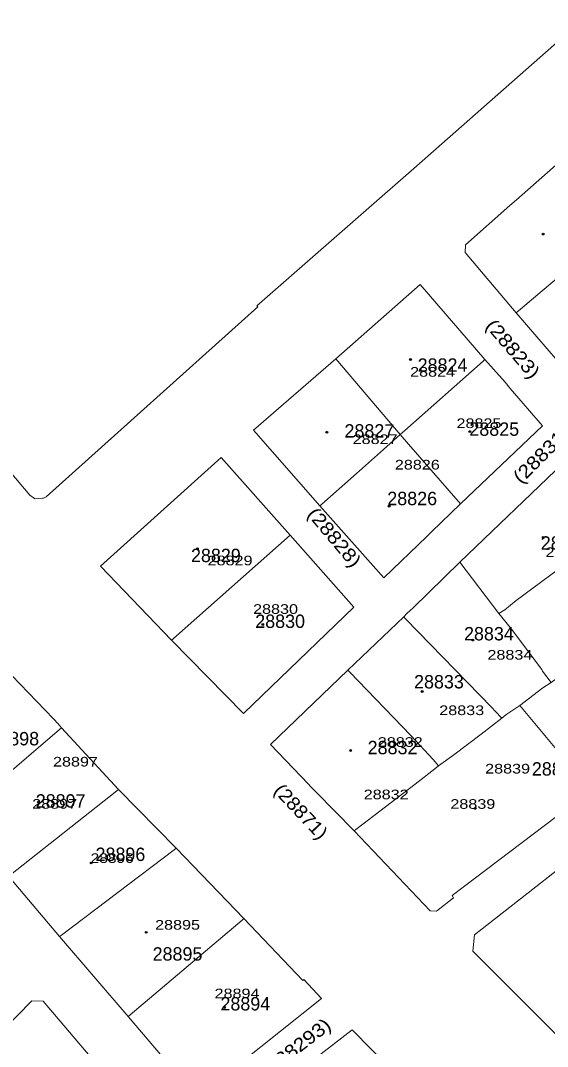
# Model space of a CAD drawing. Extents: x 650553 to 652508, y 239277 to 241647.
# Drawn here: x 650803.9 to 650945.6, y 240429.4 to 240705.5 of the extents above; entities that cross this region are included whole.
import ezdxf

# ---------------------------------------------------------------- set-up
doc = ezdxf.new("R2010")
doc.units = 0
doc.header["$PDMODE"] = 32
doc.header["$PDSIZE"] = 0.5
for name, color, linetype in [('19', 7, 'Continuous'), ('20', 7, 'Continuous'), ('6', 7, 'Continuous')]:
    doc.layers.add(name, color=color, linetype=linetype)
doc.layers.add('3', color=7, linetype='Continuous', lineweight=13)
doc.layers.add('5', color=7, linetype='Continuous', lineweight=13)

msp = doc.modelspace()

# ---------------------------------------------------------------- linework, layer by layer
at = {"layer": '3'}
for points in [[(650806.33, 240577.79), (650807.323, 240577.022), (650807.79, 240576.8), (650809.78, 240576.91), (650810.03, 240576.96), (650810.8, 240577.31), (650867.67, 240628.42), (650867.44, 240628.7), (650897.52, 240655.12), (650909.64, 240665.65), (651000, 240745.41)], [(650806.33, 240577.79), (650765.444, 240626.293), (650746.606, 240648.49), (650731.529, 240665.947), (650726.049, 240672.268), (650724.783, 240671.099), (650711.274, 240687.205), (650684, 240718.73), (650670.237, 240734.531)], [(650937.12, 240626.82), (650923.402, 240643.071), (650923.5, 240645.18), (650935.4, 240655.74), (650937.22, 240657.28), (650950.86, 240669.25)], [(650888.62, 240614.45), (650911.34, 240634.44), (650928.74, 240614.28)], [(651031.85, 240556.67), (651013.05, 240541.64), (651010.73, 240541.84), (651000, 240554), (650999.805, 240554.221), (650990.27, 240565.03), (650977.85, 240579.44), (650968.01, 240590.99), (650958.24, 240602.5), (650948.3, 240613.88), (650937.12, 240626.82)], [(650884.36, 240574.89), (650866.49, 240595.22), (650888.62, 240614.45)], [(650928.74, 240614.28), (650934.17, 240608.15), (650935.57, 240606.49), (650944.18, 240596.42), (650922.14, 240575.45)], [(650825.401, 240558.685), (650857.836, 240587.915), (650876.4, 240566.98)], [(650922, 240559.75), (650949.91, 240586.47), (650950.33, 240586.61), (650950.68, 240586.74), (650951.15, 240586.76), (650951.66, 240586.66), (650951.98, 240586.51), (650952.33, 240586.19), (650958.56, 240579.04), (650959.84, 240577.63), (650965.82, 240570.67)], [(650922.14, 240575.45), (650914.38, 240567.87), (650913.12, 240566.63), (650901.58, 240555.51), (650884.36, 240574.89)], [(650876.4, 240566.98), (650893.51, 240547.57), (650863.78, 240518.95), (650844.48, 240538.74), (650825.401, 240558.685)], [(650906.94, 240544.96), (650907.74, 240545.92), (650909.44, 240547.46), (650922, 240559.75)], [(650893.55, 240487.39), (650883.39, 240497.8), (650881.87, 240499.38), (650881.28, 240500), (650871.09, 240510.66), (650891.91, 240530.63), (650906.94, 240544.96)], [(650779.1, 240500), (650770.45, 240510.11), (650796.97, 240533.86), (650812.73, 240517.56)], [(650814.88, 240515.1), (650814.01, 240516.17), (650812.73, 240517.56)], [(650832.82, 240437.45), (650847.119, 240420.59), (650846.839, 240420.337), (650850.433, 240416.034), (650851.723, 240415.899), (650884.79, 240442.24), (650880.06, 240447.42), (650879.76, 240447.15), (650863.92, 240463.81), (650845.72, 240482.71), (650830.23, 240498.54), (650814.88, 240515.1)], [(650779.1, 240500), (650786.71, 240491.11), (650800.67, 240475.19), (650814.34, 240458.95), (650832.82, 240437.45)], [(650957.2, 240498.28), (650919.94, 240469.97), (650920.29, 240469.38), (650915.69, 240465.8), (650914, 240465.87), (650893.55, 240487.39)], [(650963.52, 240488.81), (650925.94, 240459.4), (650925.48, 240455.02), (650945.81, 240434.62), (650961.6, 240418.64), (650977.42, 240402.86), (650993.66, 240386.64), (651010.27, 240370.23), (651029.97, 240350.43), (651049.39, 240330.95), (651070.65, 240309.46), (651091.16, 240289.1)], [(650779.71, 240413.95), (650806.93, 240441.68), (650809.94, 240441.52), (650829.64, 240418.33), (650839.71, 240406.79), (650850.75, 240393.72), (650839.03, 240381.99), (650828.2, 240370.72), (650808.21, 240350.23), (650794.9, 240336.56), (650781.8, 240323.07), (650768.64, 240309.58), (650755.41, 240295.93), (650741.91, 240281.85), (650728.35, 240268.09)], [(650874.38, 240419.42), (650893.01, 240433.8), (650914.15, 240412.42), (650929.978, 240396.24), (650945.306, 240381.724)]]:
    msp.add_lwpolyline(points, dxfattribs=at)
at = {"layer": '5'}
for p, q in [((650966.06, 240651.45), (650937.12, 240626.82)), ((650905.92, 240594.12), (650907.19, 240595.14))]:
    msp.add_line(p, q, dxfattribs=at)
for points in [[(650884.36, 240574.89), (650884.86, 240575.333), (650893.41, 240582.91), (650901.46, 240590.07), (650905.92, 240594.12), (650888.62, 240614.45)], [(650907.19, 240595.14), (650928.24, 240613.836), (650928.74, 240614.28)], [(650905.92, 240594.12), (650908.16, 240591.45), (650922.14, 240575.45)], [(650965.82, 240570.67), (650965.32, 240570.299), (650955.1, 240562.71), (650937.18, 240549.44), (650934.12, 240546.91), (650932.52, 240545.92), (650922, 240559.75)], [(650844.48, 240538.74), (650844.98, 240539.182), (650876.4, 240566.98)], [(650932.52, 240545.92), (650935.59, 240542.07), (650944.06, 240530.83), (650944.26, 240530.41), (650946.54, 240527.37), (650957.28, 240535.2), (650959.14, 240536.64)], [(650930.68, 240520.49), (650907.425, 240544.46), (650906.94, 240544.96)], [(650908.81, 240513.06), (650892.391, 240530.13), (650891.91, 240530.63)], [(650946.54, 240527.37), (650944.35, 240525.89), (650938.16, 240521.11), (650952.89, 240503.37), (650955.75, 240500)], [(650938.16, 240521.11), (650935.7, 240519.49), (650934.33, 240518.62), (650933.31, 240517.77), (650931.48, 240519.65), (650930.68, 240520.49)], [(650933.31, 240517.77), (650927.76, 240513.42), (650920.36, 240507.88), (650916.3, 240504.89), (650915.3, 240504.06), (650910, 240500)], [(650797.15, 240500), (650814.38, 240514.674), (650814.88, 240515.1)], [(650916.3, 240504.89), (650914.85, 240506.63), (650908.81, 240513.06)], [(650910, 240500), (650894.05, 240487.773), (650893.55, 240487.39)], [(650830.23, 240498.54), (650829.73, 240498.145), (650801.17, 240475.585), (650800.67, 240475.19)], [(650845.72, 240482.71), (650845.22, 240482.331), (650814.84, 240459.329), (650814.34, 240458.95)], [(650863.92, 240463.81), (650863.42, 240463.386), (650833.32, 240437.874), (650832.82, 240437.45)]]:
    msp.add_lwpolyline(points, dxfattribs=at)
at = {"layer": '6'}
for p in [(650944.382, 240648.035), (650908.752, 240614.28), (650886.213, 240594.67), (650924.697, 240594.865), (650902.958, 240574.815), (650944.436, 240566.34), (650851.412, 240563.327), (650868.991, 240542.965), (650925.52, 240538.76), (650911.887, 240524.925), (650892.641, 240509.01), (650808.69, 240495.145), (650926.156, 240493.455), (650822.827, 240478.745), (650837.676, 240460.08), (650858.725, 240439.854)]:
    msp.add_point(p, dxfattribs=at)

# ---------------------------------------------------------------- texts
at = {"layer": '19'}
for s, rotation, width, p in [('(28823)', 310.689, 1.15, (650928.677, 240623.196)), ('(28831)', 44.972, 1.15, (650938.468, 240580.606)), ('(28828)', 310.151, 1.15, (650880.744, 240572.543)), ('(28871)', 313.241, 1.1, (650871.706, 240498.012)), ('(28293)', 37.664, 1.15, (650872.62, 240422.724))]:
    msp.add_text(s, height=3.6, rotation=rotation, dxfattribs=dict(at, width=width)).set_placement(p)
for s, p in [('28824', (650910.645, 240610.971)), ('28827', (650890.972, 240593.253)), ('28825', (650924.562, 240593.732)), ('28826', (650902.489, 240575.057)), ('28835', (650943.758, 240563.085)), ('28829', (650849.703, 240559.733)), ('28830', (650866.977, 240542.015)), ('28834', (650923.123, 240538.663)), ('28833', (650909.687, 240525.734)), ('28898', (650795.476, 240510.41)), ('28832', (650897.21, 240508.016)), ('28839', (650941.36, 240502.269)), ('28897', (650807.953, 240493.65)), ('28896', (650824.029, 240479.283)), ('28895', (650839.385, 240452.467)), ('28894', (650857.62, 240439.059))]:
    msp.add_text(s, height=3.6, dxfattribs=at).set_placement(p)
at = {"layer": '20'}
for s, width, p in [('28824', 1.25, (650908.615, 240609.639)), ('28825', 1.25, (650921.096, 240595.817)), ('28827', 1.25, (650893.177, 240591.511)), ('28826', 1.25, (650904.524, 240584.657)), ('28835', 1.25, (650945.009, 240561.073)), ('28829', 1.25, (650854.168, 240558.868)), ('28830', 1.25, (650866.393, 240545.802)), ('28834', 1.25, (650929.412, 240533.481)), ('28833', 1.25, (650916.46, 240518.552)), ('28832', 1.25, (650899.923, 240510.002)), ('28897', 1.25, (650812.594, 240504.711)), ('28839', 1.25, (650928.794, 240502.828)), ('28897', 1.25, (650806.982, 240493.356)), ('28832', 1.25, (650896.146, 240495.892)), ('28839', 1.25, (650919.442, 240493.326)), ('28896', 1.2, (650822.706, 240478.761)), ('28895', 1.25, (650840.045, 240460.795)), ('28894', 1.25, (650856.034, 240442.326))]:
    msp.add_text(s, height=2.6, dxfattribs=dict(at, width=width)).set_placement(p)

doc.saveas('drawing.dxf')
